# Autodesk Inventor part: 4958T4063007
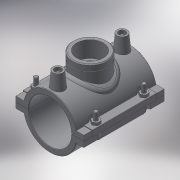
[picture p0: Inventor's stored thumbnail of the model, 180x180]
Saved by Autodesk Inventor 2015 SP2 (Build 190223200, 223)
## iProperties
Created: 2017-07
Part Number: 4958T4063007
Material: Generic
Description: PLASSON SADDLE 63X3/4" FEMALE BSPP
Document SubType Name: Modeling
Designer: KIM
Density: 1 g/cm^3
Appearance: Default
Author: KIM
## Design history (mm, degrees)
derived "4958T4.ipt"
feature "Solid1::4958T4.ipt"
tag "TaggingFeature1"
body "Solid1"
other parameters: "d0" = 63, "d1" = 78.75, "d3" = 15.75, "d4" = 118, "d5" = 0, "d6" = 0.1, "d8" = 0, "d19" = 6, "d20" = 6, "d21" = 70.8, "d23" = 0, "d24" = 35.4, "d26" = 0, "d27" = 3, "d28" = 3, "d29" = 3, "d30" = 24.00694, "d31" = 6, "d32" = 0, "d33" = 0, "d34" = 0.6, "d40" = 42.21, "d41" = 63, "d43" = 0, "d45" = 0, "d46" = 6.3, "d47" = 61.5, "d48" = 31.3521, "d50" = 0, "d51" = 24.117, "d52" = 24, "d53" = 0, "d54" = 19.2936, "d56" = 0, "d57" = -9, "d58" = 0.5, "d59" = 0.1, "d60" = 0, "d61" = 0.5, "d64" = 0.72351, "d67" = 0.63, "d70" = 15, "d72" = 0, "d73" = 6, "d75" = 5, "d76" = 0, "d77" = 3.15, "d78" = 60.5, "d79" = 15, "d80" = 47.2, "d82" = 5 deg, "d84" = 4, "d85" = 14, "d86" = 0, "d87" = 3, "d88" = 0, "d89" = 1, "d90" = 1, "d91" = 94.4, "d92" = 0, "d93" = 0.5, "d94" = 33.15789, "d_" = 63, "Rp_" = 24.117, "L_" = 118, "d_t" = 6
